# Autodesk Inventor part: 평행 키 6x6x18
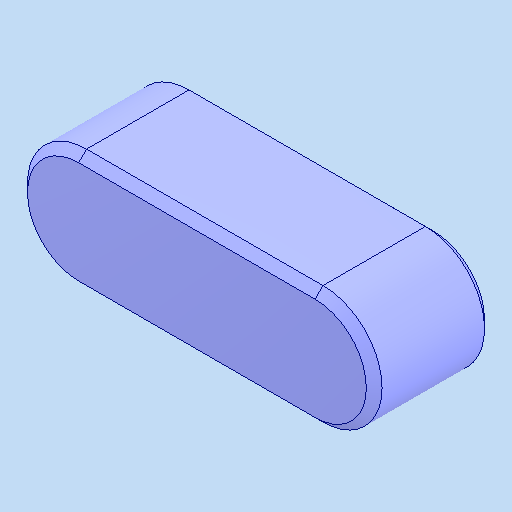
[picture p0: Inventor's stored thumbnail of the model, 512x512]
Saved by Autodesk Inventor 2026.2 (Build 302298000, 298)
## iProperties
Created: 2026-01
Part Number: 평행 키 6x6x18
Material: 강철, 연강
Description: 키 및 해당 키홈
Document SubType Name: Modeling
Designer: PC2-07
Density: 7.85 g/cm^3
Appearance: 기본값
Author: jhkim
Sending System: Autodesk Inventor 2026
Preprocessor: ST-DEVELOPER v20.1
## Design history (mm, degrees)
feature "Solid1"
node "솔리드1"
